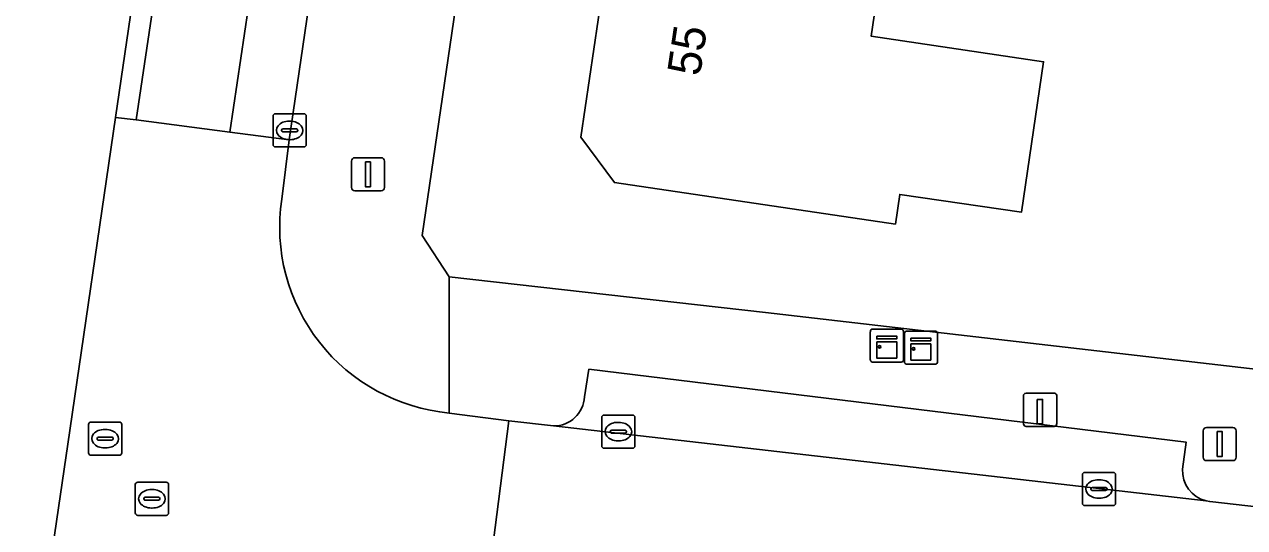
# Model space of a CAD drawing. Extents: x 162250 to 162661, y 380743 to 381606.
# Drawn here: x 162318.31 to 162355.04, y 381366.93 to 381382.1 of the extents above; entities that cross this region are included whole.
import ezdxf

# ---------------------------------------------------------------- set-up
doc = ezdxf.new("R2010")
doc.units = 0
for name, color, linetype in [('IMGEO_Erf', 7, 'Continuous'), ('IMGEO_Kast', 7, 'Continuous'), ('IMGEO_Kolk', 7, 'Continuous'), ('IMGEO_Laadpaal', 7, 'Continuous'), ('IMGEO_Lichtmast', 7, 'Continuous'), ('IMGEO_Pand', 7, 'Continuous'), ('IMGEO_Pand_nummerreeks', 7, 'Continuous'), ('IMGEO_Parkeervlak_open', 7, 'Continuous'), ('IMGEO_Rijbaan_lokaal_gesloten', 7, 'Continuous'), ('IMGEO_Rijbaan_lokaal_open', 7, 'Continuous'), ('IMGEO_Rioolput', 7, 'Continuous'), ('IMGEO_Voetpad_open', 7, 'Continuous')]:
    doc.layers.add(name, color=color, linetype=linetype)

msp = doc.modelspace()

# ---------------------------------------------------------------- linework, layer by layer
at = {"layer": 'IMGEO_Erf'}
for points in [[(162332.068, 381387.938), (162330.281, 381375.735), (162331.101, 381374.491), (162340.622, 381373.413), (162412.338, 381365.108)], [(162344.295, 381385.086), (162343.8, 381381.738), (162348.988, 381380.972), (162348.321, 381376.436), (162344.66, 381376.975), (162344.528, 381376.079), (162336.071, 381377.329), (162335.056, 381378.696), (162335.711, 381383.129)]]:
    msp.add_lwpolyline(points, dxfattribs=at)
at = {"layer": 'IMGEO_Kast'}
for p, q in [((162343.849, 381372.916), (162344.69, 381372.916)), ((162344.69, 381372.916), (162343.849, 381372.916)), ((162343.774, 381371.991), (162343.774, 381372.832)), ((162343.774, 381372.832), (162343.774, 381371.991)), ((162344.774, 381372.841), (162344.774, 381372)), ((162344.774, 381372), (162344.774, 381372.841)), ((162344.799, 381371.93), (162344.799, 381372.771)), ((162344.799, 381372.771), (162344.799, 381371.93)), ((162344.874, 381372.855), (162345.715, 381372.855)), ((162345.715, 381372.855), (162344.874, 381372.855)), ((162345.799, 381372.78), (162345.799, 381371.939)), ((162345.799, 381371.939), (162345.799, 381372.78)), ((162344.699, 381371.916), (162343.858, 381371.916)), ((162343.858, 381371.916), (162344.699, 381371.916)), ((162345.724, 381371.855), (162344.883, 381371.855)), ((162344.883, 381371.855), (162345.724, 381371.855))]:
    msp.add_line(p, q, dxfattribs=at)
for points in [[(162343.969, 381372.706), (162344.569, 381372.706), (162344.569, 381372.621), (162343.969, 381372.621), (162343.969, 381372.706)], [(162343.969, 381372.531), (162344.569, 381372.531), (162344.569, 381372.042), (162343.969, 381372.042), (162343.969, 381372.531)], [(162344.994, 381372.645), (162345.594, 381372.645), (162345.594, 381372.56), (162344.994, 381372.56), (162344.994, 381372.645)], [(162344.994, 381372.47), (162345.594, 381372.47), (162345.594, 381371.981), (162344.994, 381371.981), (162344.994, 381372.47)]]:
    msp.add_lwpolyline(points, dxfattribs=at)
for centre in [(162344.053, 381372.38), (162345.078, 381372.319)]:
    msp.add_circle(centre, 0.0377, dxfattribs=at)
for centre, start, end in [((162343.852, 381372.838), 92.4484, 184.2845), ((162343.852, 381372.838), 92.4484, 184.2845), ((162344.696, 381372.838), 2.4484, 94.2845), ((162344.696, 381372.838), 2.4484, 94.2845), ((162344.877, 381372.777), 92.4484, 184.2845), ((162344.877, 381372.777), 92.4484, 184.2845), ((162345.721, 381372.777), 2.4484, 94.2845), ((162345.721, 381372.777), 2.4484, 94.2845), ((162343.852, 381371.994), 182.4484, 274.2845), ((162343.852, 381371.994), 182.4484, 274.2845), ((162344.696, 381371.994), 272.4484, 4.2845), ((162344.696, 381371.994), 272.4484, 4.2845), ((162344.877, 381371.933), 182.4484, 274.2845), ((162344.877, 381371.933), 182.4484, 274.2845), ((162345.721, 381371.933), 272.4484, 4.2845), ((162345.721, 381371.933), 272.4484, 4.2845)]:
    msp.add_arc(centre, 0.0779, start, end, dxfattribs=at)
at = {"layer": 'IMGEO_Kolk'}
for p, q in [((162325.794, 381378.476), (162325.794, 381379.328)), ((162325.869, 381379.402), (162326.721, 381379.402)), ((162326.282, 381379.182), (162326.307, 381379.182)), ((162326.795, 381379.328), (162326.795, 381378.476)), ((162326.053, 381378.896), (162326.053, 381378.908)), ((162326.491, 381378.859), (162326.093, 381378.859)), ((162326.096, 381378.945), (162326.494, 381378.945)), ((162326.537, 381378.908), (162326.537, 381378.896)), ((162326.305, 381378.622), (162326.28, 381378.622)), ((162326.721, 381378.402), (162325.869, 381378.402)), ((162335.763, 381370.325), (162336.615, 381370.325)), ((162335.688, 381369.399), (162335.688, 381370.251)), ((162336.176, 381370.105), (162336.201, 381370.105)), ((162336.689, 381370.251), (162336.689, 381369.399)), ((162335.947, 381369.819), (162335.947, 381369.831)), ((162336.385, 381369.782), (162335.987, 381369.782)), ((162335.99, 381369.868), (162336.388, 381369.868)), ((162336.431, 381369.831), (162336.431, 381369.819)), ((162336.615, 381369.325), (162335.763, 381369.325)), ((162336.199, 381369.545), (162336.174, 381369.545)), ((162350.156, 381367.671), (162350.156, 381368.523)), ((162350.231, 381368.597), (162351.083, 381368.597)), ((162351.157, 381368.523), (162351.157, 381367.671)), ((162350.458, 381368.14), (162350.856, 381368.14)), ((162350.644, 381368.377), (162350.669, 381368.377)), ((162350.415, 381368.091), (162350.415, 381368.103)), ((162350.853, 381368.054), (162350.455, 381368.054)), ((162350.667, 381367.817), (162350.642, 381367.817)), ((162350.899, 381368.103), (162350.899, 381368.091)), ((162351.083, 381367.597), (162350.231, 381367.597))]:
    msp.add_line(p, q, dxfattribs=at)
for points in [[(162325.794, 381378.476), (162325.794, 381379.328)], [(162325.869, 381379.402), (162326.721, 381379.402)], [(162326.795, 381379.328), (162326.795, 381378.476)], [(162326.721, 381378.402), (162325.869, 381378.402)], [(162335.763, 381370.325), (162336.615, 381370.325)], [(162335.688, 381369.399), (162335.688, 381370.251)], [(162336.689, 381370.251), (162336.689, 381369.399)], [(162336.615, 381369.325), (162335.763, 381369.325)], [(162350.156, 381367.671), (162350.156, 381368.523)], [(162350.231, 381368.597), (162351.083, 381368.597)], [(162351.157, 381368.523), (162351.157, 381367.671)], [(162351.083, 381367.597), (162350.231, 381367.597)]]:
    msp.add_lwpolyline(points, dxfattribs=at)
for centre, radius, start, end in [((162325.871, 381379.326), 0.0765, 91.552, 178.448), ((162325.871, 381379.326), 0.0765, 91.552, 178.448), ((162326.719, 381379.326), 0.0765, 1.552, 88.448), ((162326.719, 381379.326), 0.0765, 1.552, 88.448), ((162326.093, 381378.905), 0.0403, 85.8775, 175.7526), ((162326.09, 381378.895), 0.0366, 178.938, 274.7102), ((162326.494, 381378.902), 0.043, 264.8664, 352.4533), ((162326.498, 381378.907), 0.0386, 1.7309, 96.639), ((162325.871, 381378.478), 0.0765, 181.552, 268.448), ((162325.871, 381378.478), 0.0765, 181.552, 268.448), ((162326.719, 381378.478), 0.0765, 271.552, 358.448), ((162326.719, 381378.478), 0.0765, 271.552, 358.448), ((162335.765, 381370.249), 0.0765, 91.552, 178.448), ((162335.765, 381370.249), 0.0765, 91.552, 178.448), ((162336.613, 381370.249), 0.0765, 1.552, 88.448), ((162336.613, 381370.249), 0.0765, 1.552, 88.448), ((162335.987, 381369.828), 0.0403, 85.8775, 175.7526), ((162335.984, 381369.818), 0.0366, 178.938, 274.7102), ((162336.388, 381369.825), 0.043, 264.8664, 352.4533), ((162336.392, 381369.83), 0.0386, 1.7309, 96.639), ((162335.765, 381369.401), 0.0765, 181.552, 268.448), ((162335.765, 381369.401), 0.0765, 181.552, 268.448), ((162336.613, 381369.401), 0.0765, 271.552, 358.448), ((162336.613, 381369.401), 0.0765, 271.552, 358.448), ((162350.233, 381368.521), 0.0765, 91.552, 178.448), ((162350.233, 381368.521), 0.0765, 91.552, 178.448), ((162351.081, 381368.521), 0.0765, 1.552, 88.448), ((162351.081, 381368.521), 0.0765, 1.552, 88.448), ((162350.455, 381368.1), 0.0403, 85.8775, 175.7526), ((162350.86, 381368.102), 0.0386, 1.7309, 96.639), ((162350.452, 381368.09), 0.0366, 178.938, 274.7102), ((162350.856, 381368.097), 0.043, 264.8664, 352.4533), ((162350.233, 381367.673), 0.0765, 181.552, 268.448), ((162350.233, 381367.673), 0.0765, 181.552, 268.448), ((162351.081, 381367.673), 0.0765, 271.552, 358.448), ((162351.081, 381367.673), 0.0765, 271.552, 358.448)]:
    msp.add_arc(centre, radius, start, end, dxfattribs=at)
for centre, major_axis, ratio, start_param, end_param in [((162326.281, 381378.902), (-0.387, 0.002), 0.722429, 4.712389, 7.853982), ((162326.306, 381378.902), (-0.39, 0.002), 0.717154, 1.570796, 4.712389), ((162336.175, 381369.825), (-0.387, 0.002), 0.722429, 4.712389, 7.853982), ((162336.2, 381369.825), (-0.39, 0.002), 0.717154, 1.570796, 4.712389), ((162350.643, 381368.097), (-0.387, 0.002), 0.722429, 4.712389, 7.853982), ((162350.668, 381368.097), (-0.39, 0.002), 0.717154, 1.570796, 4.712389)]:
    msp.add_ellipse(centre, major_axis=major_axis, ratio=ratio, start_param=start_param, end_param=end_param, dxfattribs=at)
at = {"layer": 'IMGEO_Laadpaal'}
for p, q in [((162348.385, 381370.9), (162348.385, 381370.059)), ((162348.385, 381370.9), (162348.385, 381370.059)), ((162349.301, 381370.984), (162348.46, 381370.984)), ((162349.301, 381370.984), (162348.46, 381370.984)), ((162349.385, 381370.068), (162349.385, 381370.909)), ((162349.385, 381370.068), (162349.385, 381370.909)), ((162348.469, 381369.984), (162349.31, 381369.984)), ((162348.469, 381369.984), (162349.31, 381369.984))]:
    msp.add_line(p, q, dxfattribs=at)
msp.add_lwpolyline([(162348.8, 381370.797), (162348.96, 381370.797), (162348.96, 381370.064), (162348.8, 381370.064), (162348.8, 381370.797)], dxfattribs=at)
for centre, start, end in [((162348.463, 381370.906), 92.4484, 184.2845), ((162348.463, 381370.906), 92.4484, 184.2845), ((162349.307, 381370.906), 2.4484, 94.2845), ((162349.307, 381370.906), 2.4484, 94.2845), ((162348.463, 381370.062), 182.4484, 274.2845), ((162348.463, 381370.062), 182.4484, 274.2845), ((162349.307, 381370.062), 272.4484, 4.2845), ((162349.307, 381370.062), 272.4484, 4.2845)]:
    msp.add_arc(centre, 0.0779, start, end, dxfattribs=at)
at = {"layer": 'IMGEO_Lichtmast'}
for p, q in [((162328.257, 381378.078), (162329.047, 381378.078)), ((162329.047, 381378.078), (162328.257, 381378.078)), ((162328.157, 381377.178), (162328.157, 381377.978)), ((162328.157, 381377.978), (162328.157, 381377.178)), ((162329.147, 381377.978), (162329.147, 381377.178)), ((162329.147, 381377.178), (162329.147, 381377.978)), ((162329.047, 381377.078), (162328.257, 381377.078)), ((162328.257, 381377.078), (162329.047, 381377.078)), ((162353.795, 381369.051), (162353.795, 381369.851)), ((162353.795, 381369.851), (162353.795, 381369.051)), ((162353.895, 381369.951), (162354.685, 381369.951)), ((162354.685, 381369.951), (162353.895, 381369.951)), ((162354.785, 381369.851), (162354.785, 381369.051)), ((162354.785, 381369.051), (162354.785, 381369.851)), ((162354.685, 381368.951), (162353.895, 381368.951)), ((162353.895, 381368.951), (162354.685, 381368.951))]:
    msp.add_line(p, q, dxfattribs=at)
for points in [[(162328.577, 381377.953), (162328.727, 381377.953), (162328.727, 381377.203), (162328.577, 381377.203), (162328.577, 381377.953)], [(162354.215, 381369.826), (162354.365, 381369.826), (162354.365, 381369.076), (162354.215, 381369.076), (162354.215, 381369.826)]]:
    msp.add_lwpolyline(points, dxfattribs=at)
for centre, start, end in [((162328.257, 381377.978), 90, 180), ((162328.257, 381377.978), 90, 180), ((162329.047, 381377.978), 0, 90), ((162329.047, 381377.978), 360, 90), ((162328.257, 381377.178), 180, 270), ((162328.257, 381377.178), 180, 270), ((162329.047, 381377.178), 270, 0), ((162329.047, 381377.178), 270, 0), ((162353.895, 381369.851), 90, 180), ((162353.895, 381369.851), 90, 180), ((162354.685, 381369.851), 0, 90), ((162354.685, 381369.851), 360, 90), ((162353.895, 381369.051), 180, 270), ((162353.895, 381369.051), 180, 270), ((162354.685, 381369.051), 270, 0), ((162354.685, 381369.051), 270, 0)]:
    msp.add_arc(centre, 0.1, start, end, dxfattribs=at)
at = {"layer": 'IMGEO_Pand'}
msp.add_lwpolyline([(162344.295, 381385.086), (162343.896, 381384.983), (162336.163, 381386.115), (162336.054, 381385.378), (162335.501, 381384.968), (162335.309, 381383.67), (162335.711, 381383.129), (162335.056, 381378.696), (162336.071, 381377.329), (162344.528, 381376.079), (162344.66, 381376.975), (162348.321, 381376.436), (162348.988, 381380.972), (162343.8, 381381.738)], close=True, dxfattribs=at)
at = {"layer": 'IMGEO_Parkeervlak_open'}
for points in [[(162353.17, 381368.697), (162353.278, 381369.51), (162335.305, 381371.705), (162335.166, 381370.874)], [(162334.237, 381369.996), (162353.883, 381367.738)]]:
    msp.add_lwpolyline(points, dxfattribs=at)
for centre, radius, start, end in [((162334.251, 381370.912), 0.916, 269.1147, 357.6519), ((162354.111, 381368.652), 0.942, 177.2703, 255.9901)]:
    msp.add_arc(centre, radius, start, end, dxfattribs=at)
at = {"layer": 'IMGEO_Rijbaan_lokaal_gesloten'}
for points in [[(162321.057, 381379.295), (162321.057, 381379.295), (162321.673, 381379.215), (162345.986, 381542.729), (162344.886, 381542.888), (162337.941, 381494.596)], [(162342.842, 381489.774), (162343.13, 381491.968), (162349.998, 381538.218), (162350.562, 381542.047), (162348.846, 381542.303), (162344.03, 381510.414), (162324.497, 381378.848), (162326.277, 381378.617), (162326.988, 381383.502), (162328.79, 381395.572), (162328.878, 381396.23), (162335.68, 381441.768), (162335.989, 381444.267)]]:
    msp.add_lwpolyline(points, close=True, dxfattribs=at)
at = {"layer": 'IMGEO_Rijbaan_lokaal_open'}
for points in [[(162321.673, 381379.215), (162324.497, 381378.848), (162344.03, 381510.414), (162348.846, 381542.303), (162345.986, 381542.729)], [(162355.136, 381367.589), (162353.99, 381367.718), (162353.883, 381367.738), (162334.237, 381369.996), (162332.888, 381370.148), (162332.334, 381365.76), (162333.525, 381365.596), (162335.576, 381365.429), (162352.274, 381363.417), (162354.574, 381363.147), (162360.607, 381362.439), (162370.812, 381361.312), (162371.314, 381365.763)]]:
    msp.add_lwpolyline(points, close=True, dxfattribs=at)
for points in [[(162326.057, 381376.827), (162326.277, 381378.617), (162324.497, 381378.848), (162321.673, 381379.215), (162321.057, 381379.295), (162321.057, 381379.295), (162319.615, 381369.448), (162318.31, 381360.535)], [(162330.579, 381365.92), (162332.334, 381365.76), (162332.888, 381370.148), (162331.099, 381370.386)]]:
    msp.add_lwpolyline(points, dxfattribs=at)
msp.add_arc((162331.617, 381375.985), 5.623, 171.3899, 264.7176, dxfattribs=at)
at = {"layer": 'IMGEO_Rioolput'}
for p, q in [((162320.24, 381369.187), (162320.24, 381370.039)), ((162320.315, 381370.113), (162321.167, 381370.113)), ((162321.241, 381370.039), (162321.241, 381369.187)), ((162320.499, 381369.607), (162320.499, 381369.619)), ((162320.542, 381369.656), (162320.94, 381369.656)), ((162320.728, 381369.893), (162320.753, 381369.893)), ((162320.983, 381369.619), (162320.983, 381369.607)), ((162320.937, 381369.57), (162320.539, 381369.57)), ((162320.751, 381369.333), (162320.726, 381369.333)), ((162321.167, 381369.113), (162320.315, 381369.113)), ((162321.648, 381367.377), (162321.648, 381368.229)), ((162321.723, 381368.303), (162322.575, 381368.303)), ((162322.649, 381368.229), (162322.649, 381367.377)), ((162321.907, 381367.797), (162321.907, 381367.809)), ((162322.345, 381367.76), (162321.947, 381367.76)), ((162321.95, 381367.846), (162322.348, 381367.846)), ((162322.136, 381368.083), (162322.161, 381368.083)), ((162322.391, 381367.809), (162322.391, 381367.797)), ((162322.159, 381367.523), (162322.134, 381367.523)), ((162322.575, 381367.303), (162321.723, 381367.303))]:
    msp.add_line(p, q, dxfattribs=at)
for points in [[(162320.24, 381369.187), (162320.24, 381370.039)], [(162320.315, 381370.113), (162321.167, 381370.113)], [(162321.241, 381370.039), (162321.241, 381369.187)], [(162321.167, 381369.113), (162320.315, 381369.113)], [(162321.648, 381367.377), (162321.648, 381368.229)], [(162321.723, 381368.303), (162322.575, 381368.303)], [(162322.649, 381368.229), (162322.649, 381367.377)], [(162322.575, 381367.303), (162321.723, 381367.303)]]:
    msp.add_lwpolyline(points, dxfattribs=at)
for centre, radius, start, end in [((162320.317, 381370.037), 0.0765, 91.552, 178.448), ((162320.317, 381370.037), 0.0765, 91.552, 178.448), ((162321.165, 381370.037), 0.0765, 1.552, 88.448), ((162321.165, 381370.037), 0.0765, 1.552, 88.448), ((162320.539, 381369.616), 0.0403, 85.8775, 175.7526), ((162320.536, 381369.606), 0.0366, 178.938, 274.7102), ((162320.94, 381369.613), 0.043, 264.8664, 352.4533), ((162320.944, 381369.618), 0.0386, 1.7309, 96.639), ((162320.317, 381369.189), 0.0765, 181.552, 268.448), ((162320.317, 381369.189), 0.0765, 181.552, 268.448), ((162321.165, 381369.189), 0.0765, 271.552, 358.448), ((162321.165, 381369.189), 0.0765, 271.552, 358.448), ((162321.725, 381368.227), 0.0765, 91.552, 178.448), ((162321.725, 381368.227), 0.0765, 91.552, 178.448), ((162322.573, 381368.227), 0.0765, 1.552, 88.448), ((162322.573, 381368.227), 0.0765, 1.552, 88.448), ((162321.947, 381367.806), 0.0403, 85.8775, 175.7526), ((162321.944, 381367.796), 0.0366, 178.938, 274.7102), ((162322.348, 381367.803), 0.043, 264.8664, 352.4533), ((162322.352, 381367.808), 0.0386, 1.7309, 96.639), ((162321.725, 381367.379), 0.0765, 181.552, 268.448), ((162321.725, 381367.379), 0.0765, 181.552, 268.448), ((162322.573, 381367.379), 0.0765, 271.552, 358.448), ((162322.573, 381367.379), 0.0765, 271.552, 358.448)]:
    msp.add_arc(centre, radius, start, end, dxfattribs=at)
for centre, major_axis, ratio, start_param, end_param in [((162320.727, 381369.613), (-0.387, 0.002), 0.722429, 4.712389, 7.853982), ((162320.752, 381369.613), (-0.39, 0.002), 0.717154, 1.570796, 4.712389), ((162322.135, 381367.803), (-0.387, 0.002), 0.722429, 4.712389, 7.853982), ((162322.16, 381367.803), (-0.39, 0.002), 0.717154, 1.570796, 4.712389)]:
    msp.add_ellipse(centre, major_axis=major_axis, ratio=ratio, start_param=start_param, end_param=end_param, dxfattribs=at)
at = {"layer": 'IMGEO_Voetpad_open'}
for points in [[(162331.099, 381370.386), (162331.101, 381374.491), (162330.281, 381375.735), (162332.068, 381387.938), (162332.211, 381387.945), (162334.576, 381404.093), (162334.728, 381405.133), (162338.89, 381433.553), (162339.214, 381435.764), (162339.996, 381441.104), (162343.449, 381463.697), (162345.762, 381479.541), (162345.951, 381480.835), (162350.479, 381511.856), (162350.791, 381513.94), (162350.929, 381514.861), (162358.055, 381562.41), (162359.403, 381573.306), (162359.448, 381578.123), (162362.669, 381579.584), (162363.286, 381580.314), (162361.6, 381584.081), (162363.369, 381585.251), (162370.283, 381588.375)], [(162326.988, 381383.502), (162326.277, 381378.617), (162326.057, 381376.827)], [(162340.622, 381373.413), (162331.101, 381374.491), (162331.099, 381370.386), (162332.888, 381370.148), (162334.237, 381369.996)], [(162424.743, 381363.694), (162412.338, 381365.108), (162340.622, 381373.413)], [(162335.166, 381370.874), (162335.305, 381371.705), (162353.278, 381369.51), (162353.17, 381368.697)], [(162353.883, 381367.738), (162353.99, 381367.718), (162355.136, 381367.589)]]:
    msp.add_lwpolyline(points, dxfattribs=at)
for centre, radius, start, end in [((162331.617, 381375.985), 5.623, 171.3899, 264.7176), ((162334.251, 381370.912), 0.916, 269.1147, 357.6519), ((162354.111, 381368.652), 0.942, 177.2703, 255.9901)]:
    msp.add_arc(centre, radius, start, end, dxfattribs=at)

# ---------------------------------------------------------------- texts
at = {"layer": 'IMGEO_Pand_nummerreeks'}
msp.add_text('55', height=1, rotation=81.5251, dxfattribs=at).set_placement((162338.644, 381380.51))

doc.saveas('drawing.dxf')
